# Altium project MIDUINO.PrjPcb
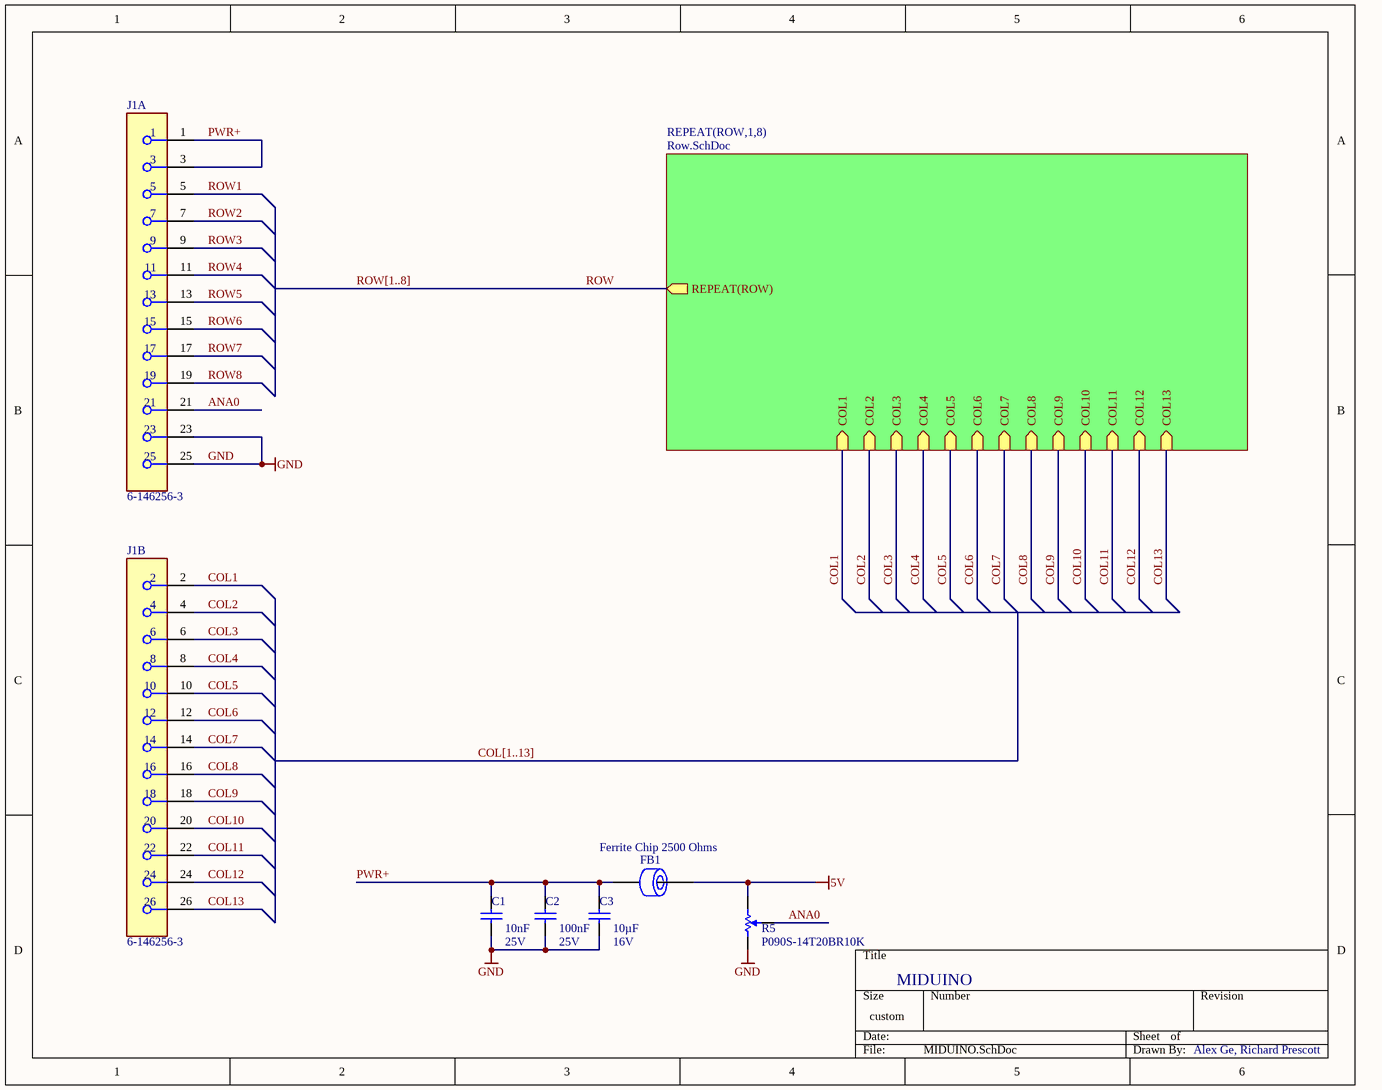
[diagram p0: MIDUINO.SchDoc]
2 sheets, 230 parts. Net scope: hierarchical (ports join the sheet entries above them; power ports are global).
Board file: MIDUINO.PcbDoc
Sheets:
  MIDUINO.SchDoc
    ROW1 = Row.SchDoc
    ROW2 = Row.SchDoc
    ROW3 = Row.SchDoc
    ROW4 = Row.SchDoc
    ROW5 = Row.SchDoc
    ROW6 = Row.SchDoc
    ROW7 = Row.SchDoc
    ROW8 = Row.SchDoc

## Sheet MIDUINO.SchDoc
size 254 x 203 mm; SheetNumber: 1; SheetTotal: 2

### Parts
C1  Val: 10nF  Vol: 25V  [0603_CAP]  (hidden comment: CAP 0603 0.01UF 25V 10% X7R)
C2  Val: 100nF  Vol: 25V  [0603_CAP]  (hidden comment: CAP 0603 0.1UF 25V 10% X7R)
C3  Val: 10µF  Vol: 16V  [0805_CAP_60H]  (hidden comment: CAP 0805 10UF 16V 20% X7R)
FB1  Ferrite Chip 2500 Ohms  [0603]
J1  6-146256-3  [FP-6-146256-3-MFG]  (parts A,B of 2)
R5  P090S-14T20BR10K  [RES-POT-3]

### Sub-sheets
REPEAT(ROW,1,8) = Row.SchDoc: COL1 (in), COL2 (in), COL3 (in), COL4 (in), COL5 (in), COL6 (in), COL7 (in), COL8 (in), COL9 (in), COL10 (in), COL11 (in), COL12 (in), COL13 (in), REPEAT(ROW) (out)

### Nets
5V: FB1.1 R5.3
GND: C1.1 C2.2 C3.1 J1.23 J1.25 R5.1
ANA0: J1.21 R5.2
COL1: J1.2 ; sheet REPEAT(ROW,1,8)/COL1
COL2: J1.4 ; sheet REPEAT(ROW,1,8)/COL2
COL3: J1.6 ; sheet REPEAT(ROW,1,8)/COL3
COL4: J1.8 ; sheet REPEAT(ROW,1,8)/COL4
COL5: J1.10 ; sheet REPEAT(ROW,1,8)/COL5
COL6: J1.12 ; sheet REPEAT(ROW,1,8)/COL6
COL7: J1.14 ; sheet REPEAT(ROW,1,8)/COL7
COL8: J1.16 ; sheet REPEAT(ROW,1,8)/COL8
COL9: J1.18 ; sheet REPEAT(ROW,1,8)/COL9
COL10: J1.20 ; sheet REPEAT(ROW,1,8)/COL10
COL11: J1.22 ; sheet REPEAT(ROW,1,8)/COL11
COL12: J1.24 ; sheet REPEAT(ROW,1,8)/COL12
COL13: J1.26 ; sheet REPEAT(ROW,1,8)/COL13
PWR+: C1.2 C2.1 C3.2 FB1.2 J1.1 J1.3
ROW1: J1.5  [project net ROW]
ROW2: J1.7  [project net ROW]
ROW3: J1.9  [project net ROW]
ROW4: J1.11  [project net ROW]
ROW5: J1.13  [project net ROW]
ROW6: J1.15  [project net ROW]
ROW7: J1.17  [project net ROW]
ROW8: J1.19  [project net ROW]

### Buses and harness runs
bus COL[1..13]
bus ROW[1..8]

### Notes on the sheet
- MIDUINO
- Alex Ge, Richard Prescott

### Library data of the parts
C1 = CAP 0603 0.01UF 25V 10% X7R-2: Capacitor Surface Mount 0603 Footprint 0.01UF 25V 10% Tolerance Ceramic X7R; Manufacturer: Various; PCB Package: 0603; Description in Visual: Cap SMT 0603 0.01UF 25V 10%  Cer X7R; Value: 10nF
C2 = CAP 0603 0.1UF 25V 10% X7R-4: Capacitor Surface Mount 0603 Footprint 0.1UF 25V 10% Tolerance Ceramic X7R; Manufacturer: Various; PCB Package: 0603; Description in Visual: Cap SMT 0603 0.1UF 25V 10%  Cer X7R; Value: 100nF
C3 = CAP 0805 10UF 16V 20% X7R-2: Capacitor Surface Mount 0805 Footprint 10UF 16V 20% Tolerance Ceramic X7R; Manufacturer: Various; PCB Package: 0805; Description in Visual: Cap SMT 0805 10UF 16V 20% Ceramic X7R; Value: 10µF
FB1 = MMZ1608A252B-2: Ferrite Chip 200 mA 2500 Ohms Differential Mode - Single 0603 Footprint; Manufacturer: TDK; Description in Visual: Ferrite SMT 200mA 2500Ohm Dif Mode 0603; Usage: Signal Line; Current (mA): 200; Frequency: 100 MHz; Impedance at Freq (ohms): 2500; DC Resistance (ohms): 0.8
J1 = CMP-03369-000069-1: CONN HEADER VERT 26POS 2.54MM; Manufacturer: TE Connectivity; Current Rating: 3A; Is Female: yes; Conn Gender: Male; Number Of Contacts: 26; Voltage Rating: 30V; Conn Orientation: Vertical
R5 = CMP-2000-06871-1: 9 mm Rotary Potentiometer, Insulated Shaft, Conductive Plastic Element, 10 KOhm, -20 to 70 degC, 3-Pin THD, RoHS, Tray; Manufacturer: BI Technologies; Actuator Type: Knurled; Power Rating: 0.03W; Tolerance: ±20%; Actuator Diameter: 0.236"(6.00mm); Other Names: 987-1277P090S14T20BR10K; Actuator Length: 0.787"(20.00mm); Number of Gangs: 1; Online Catalog: P090Series; Power (Watts): 0.03W,1/32W; Built in Switch: Detent; Resistance (Ohms): 10k; Adjustment Type: TopAdjustment; Rotation: 280°

## Sheet Row.SchDoc
size 228 x 152 mm; SheetNumber: 2; SheetTotal: 2
Used 8 times, as channels ROW1, ROW2, ROW3, ROW4, ROW5, ROW6, ROW7, ROW8. Parts and nets are listed once, with the designators drawn on the sheet.
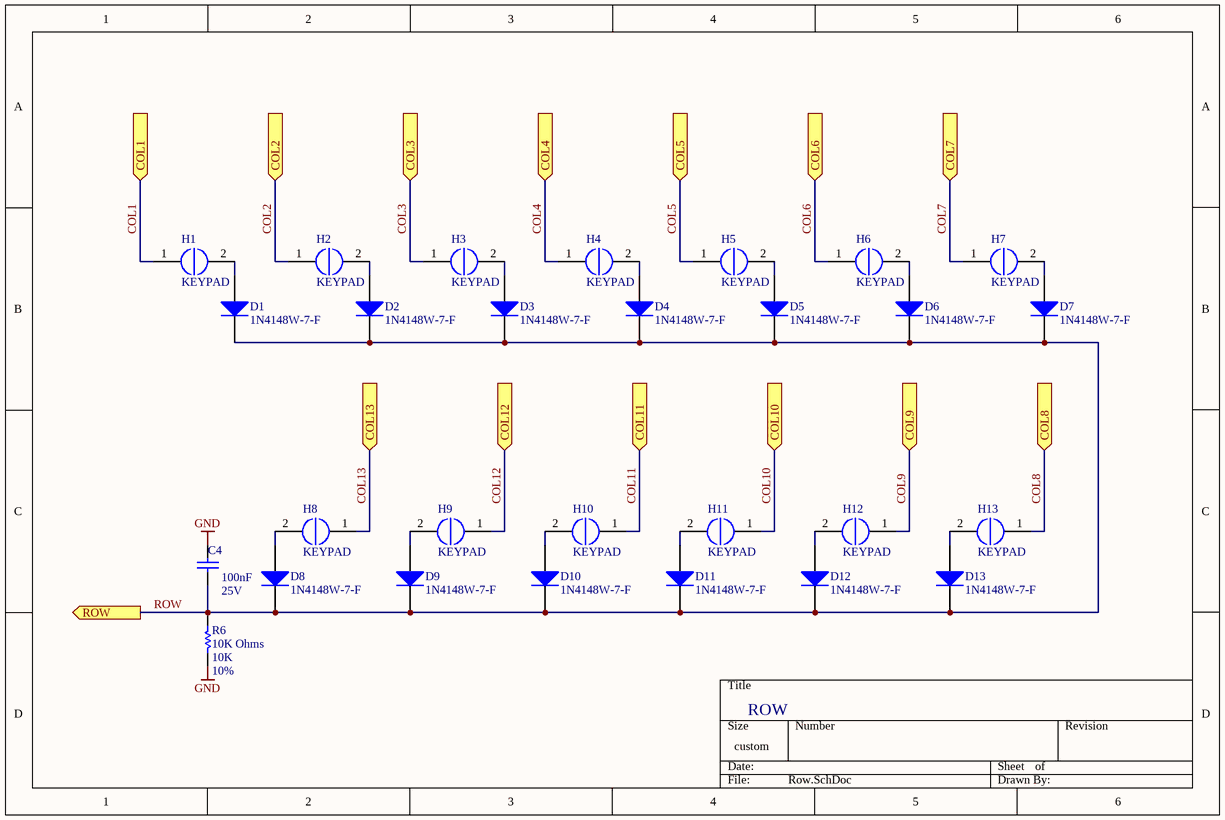
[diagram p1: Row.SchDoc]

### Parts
C4  Val: 100nF  Vol: 25V  [0603_CAP]  (hidden comment: CAP 0603 0.1UF 25V 10% X7R)
D1  1N4148W-7-F  [DIOD-SOD123-2_V]
D2  1N4148W-7-F  [DIOD-SOD123-2_V]
D3  1N4148W-7-F  [DIOD-SOD123-2_V]
D4  1N4148W-7-F  [DIOD-SOD123-2_V]
D5  1N4148W-7-F  [DIOD-SOD123-2_V]
D6  1N4148W-7-F  [DIOD-SOD123-2_V]
D7  1N4148W-7-F  [DIOD-SOD123-2_V]
D8  1N4148W-7-F  [DIOD-SOD123-2_V]
D9  1N4148W-7-F  [DIOD-SOD123-2_V]
D10  1N4148W-7-F  [DIOD-SOD123-2_V]
D11  1N4148W-7-F  [DIOD-SOD123-2_V]
D12  1N4148W-7-F  [DIOD-SOD123-2_V]
D13  1N4148W-7-F  [DIOD-SOD123-2_V]
H1  KEYPAD  [KEYPAD-Footprint-1]
H2  KEYPAD  [KEYPAD-Footprint-1]
H3  KEYPAD  [KEYPAD-Footprint-1]
H4  KEYPAD  [KEYPAD-Footprint-1]
H5  KEYPAD  [KEYPAD-Footprint-1]
H6  KEYPAD  [KEYPAD-Footprint-1]
H7  KEYPAD  [KEYPAD-Footprint-1]
H8  KEYPAD  [KEYPAD-Footprint-1]
H9  KEYPAD  [KEYPAD-Footprint-1]
H10  KEYPAD  [KEYPAD-Footprint-1]
H11  KEYPAD  [KEYPAD-Footprint-1]
H12  KEYPAD  [KEYPAD-Footprint-1]
H13  KEYPAD  [KEYPAD-Footprint-1]
R6  10K Ohms  Val: 10K  Tol: 10%  [0603_RES]

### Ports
COL1 (in), COL2 (in), COL3 (in), COL4 (in), COL5 (in), COL6 (in), COL7 (in), COL8 (in), COL9 (in), COL10 (in), COL11 (in), COL12 (in), COL13 (in), ROW (out)

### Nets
GND: C4.1 R6.1
COL1: H1.1 ; port COL1
COL2: H2.1 ; port COL2
COL3: H3.1 ; port COL3
COL4: H4.1 ; port COL4
COL5: H5.1 ; port COL5
COL6: H6.1 ; port COL6
COL7: H7.1 ; port COL7
COL8: H13.1 ; port COL8
COL9: H12.1 ; port COL9
COL10: H11.1 ; port COL10
COL11: H10.1 ; port COL11
COL12: H9.1 ; port COL12
COL13: H8.1 ; port COL13
ROW: C4.2 D1.2(K) D2.2(K) D3.2(K) D4.2(K) D5.2(K) D6.2(K) D7.2(K) D8.2(K) D9.2(K) D10.2(K) D11.2(K) D12.2(K) D13.2(K) R6.2 ; port ROW
NetD1_1: D1.1(A) H1.2
NetD2_1: D2.1(A) H2.2
NetD3_1: D3.1(A) H3.2
NetD4_1: D4.1(A) H4.2
NetD5_1: D5.1(A) H5.2
NetD6_1: D6.1(A) H6.2
NetD7_1: D7.1(A) H7.2
NetD8_1: D8.1(A) H8.2
NetD9_1: D9.1(A) H9.2
NetD10_1: D10.1(A) H10.2
NetD11_1: D11.1(A) H11.2
NetD12_1: D12.1(A) H12.2
NetD13_1: D13.1(A) H13.2

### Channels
ROW1: designators end in _ROW1; ports COL1=COL1 COL2=COL2 COL3=COL3 COL4=COL4 COL5=COL5 COL6=COL6 COL7=COL7 COL8=COL8 COL9=COL9 COL10=COL10 COL11=COL11 COL12=COL12 COL13=COL13 ROW=ROW
ROW2: designators end in _ROW2; ports COL1=COL1 COL2=COL2 COL3=COL3 COL4=COL4 COL5=COL5 COL6=COL6 COL7=COL7 COL8=COL8 COL9=COL9 COL10=COL10 COL11=COL11 COL12=COL12 COL13=COL13 ROW=ROW
ROW3: designators end in _ROW3; ports COL1=COL1 COL2=COL2 COL3=COL3 COL4=COL4 COL5=COL5 COL6=COL6 COL7=COL7 COL8=COL8 COL9=COL9 COL10=COL10 COL11=COL11 COL12=COL12 COL13=COL13 ROW=ROW
ROW4: designators end in _ROW4; ports COL1=COL1 COL2=COL2 COL3=COL3 COL4=COL4 COL5=COL5 COL6=COL6 COL7=COL7 COL8=COL8 COL9=COL9 COL10=COL10 COL11=COL11 COL12=COL12 COL13=COL13 ROW=ROW
ROW5: designators end in _ROW5; ports COL1=COL1 COL2=COL2 COL3=COL3 COL4=COL4 COL5=COL5 COL6=COL6 COL7=COL7 COL8=COL8 COL9=COL9 COL10=COL10 COL11=COL11 COL12=COL12 COL13=COL13 ROW=ROW
ROW6: designators end in _ROW6; ports COL1=COL1 COL2=COL2 COL3=COL3 COL4=COL4 COL5=COL5 COL6=COL6 COL7=COL7 COL8=COL8 COL9=COL9 COL10=COL10 COL11=COL11 COL12=COL12 COL13=COL13 ROW=ROW
ROW7: designators end in _ROW7; ports COL1=COL1 COL2=COL2 COL3=COL3 COL4=COL4 COL5=COL5 COL6=COL6 COL7=COL7 COL8=COL8 COL9=COL9 COL10=COL10 COL11=COL11 COL12=COL12 COL13=COL13 ROW=ROW
ROW8: designators end in _ROW8; ports COL1=COL1 COL2=COL2 COL3=COL3 COL4=COL4 COL5=COL5 COL6=COL6 COL7=COL7 COL8=COL8 COL9=COL9 COL10=COL10 COL11=COL11 COL12=COL12 COL13=COL13 ROW=ROW

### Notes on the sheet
- ROW

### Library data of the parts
C4 = CAP 0603 0.1UF 25V 10% X7R-4: as C2 on sheet MIDUINO
D1-D13 = CMP-2000-04932-2: Fast Switching Diode, 100 V, 0.15 A, -65 to 150 degC, 2-Pin?SOD123, RoHS, Tape and Reel; Recovery Time: 4ns; Brand: DiodesIncorporated; Unit Weight: 0.000353oz; Max Surge Current: 2A; Peak Reverse Voltage: 100V; Ir - Reverse Current: 1uA; Vf - Forward Voltage: 1.25V; Configuration: Single; If - Forward Current: 0.15A
H1-H13 = CMP-00322-7: Piano keypad
R6 = RES 0603 10K 10%-1: Resistor Surface Mount, 10K Ohms, 0603 Footprint, 10% Tolerance 0.1W; Manufacturer P/N: Various; Description in Visual: Res SMT 10K 0603  10%  0.1W; PCB Package: 0603

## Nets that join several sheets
GND: MIDUINO (6 pins), ROW1 (C4_ROW1.1 R6_ROW1.1), ROW2 (C4_ROW2.1 R6_ROW2.1), ROW3 (C4_ROW3.1 R6_ROW3.1), ROW4 (C4_ROW4.1 R6_ROW4.1), ROW5 (C4_ROW5.1 R6_ROW5.1), ROW6 (C4_ROW6.1 R6_ROW6.1), ROW7 (C4_ROW7.1 R6_ROW7.1), ROW8 (C4_ROW8.1 R6_ROW8.1)
COL1: MIDUINO (J1.2), ROW1 (H1_ROW1.1), ROW2 (H1_ROW2.1), ROW3 (H1_ROW3.1), ROW4 (H1_ROW4.1), ROW5 (H1_ROW5.1), ROW6 (H1_ROW6.1), ROW7 (H1_ROW7.1), ROW8 (H1_ROW8.1)
COL2: MIDUINO (J1.4), ROW1 (H2_ROW1.1), ROW2 (H2_ROW2.1), ROW3 (H2_ROW3.1), ROW4 (H2_ROW4.1), ROW5 (H2_ROW5.1), ROW6 (H2_ROW6.1), ROW7 (H2_ROW7.1), ROW8 (H2_ROW8.1)
COL3: MIDUINO (J1.6), ROW1 (H3_ROW1.1), ROW2 (H3_ROW2.1), ROW3 (H3_ROW3.1), ROW4 (H3_ROW4.1), ROW5 (H3_ROW5.1), ROW6 (H3_ROW6.1), ROW7 (H3_ROW7.1), ROW8 (H3_ROW8.1)
COL4: MIDUINO (J1.8), ROW1 (H4_ROW1.1), ROW2 (H4_ROW2.1), ROW3 (H4_ROW3.1), ROW4 (H4_ROW4.1), ROW5 (H4_ROW5.1), ROW6 (H4_ROW6.1), ROW7 (H4_ROW7.1), ROW8 (H4_ROW8.1)
COL5: MIDUINO (J1.10), ROW1 (H5_ROW1.1), ROW2 (H5_ROW2.1), ROW3 (H5_ROW3.1), ROW4 (H5_ROW4.1), ROW5 (H5_ROW5.1), ROW6 (H5_ROW6.1), ROW7 (H5_ROW7.1), ROW8 (H5_ROW8.1)
COL6: MIDUINO (J1.12), ROW1 (H6_ROW1.1), ROW2 (H6_ROW2.1), ROW3 (H6_ROW3.1), ROW4 (H6_ROW4.1), ROW5 (H6_ROW5.1), ROW6 (H6_ROW6.1), ROW7 (H6_ROW7.1), ROW8 (H6_ROW8.1)
COL7: MIDUINO (J1.14), ROW1 (H7_ROW1.1), ROW2 (H7_ROW2.1), ROW3 (H7_ROW3.1), ROW4 (H7_ROW4.1), ROW5 (H7_ROW5.1), ROW6 (H7_ROW6.1), ROW7 (H7_ROW7.1), ROW8 (H7_ROW8.1)
COL8: MIDUINO (J1.16), ROW1 (H13_ROW1.1), ROW2 (H13_ROW2.1), ROW3 (H13_ROW3.1), ROW4 (H13_ROW4.1), ROW5 (H13_ROW5.1), ROW6 (H13_ROW6.1), ROW7 (H13_ROW7.1), ROW8 (H13_ROW8.1)
COL9: MIDUINO (J1.18), ROW1 (H12_ROW1.1), ROW2 (H12_ROW2.1), ROW3 (H12_ROW3.1), ROW4 (H12_ROW4.1), ROW5 (H12_ROW5.1), ROW6 (H12_ROW6.1), ROW7 (H12_ROW7.1), ROW8 (H12_ROW8.1)
COL10: MIDUINO (J1.20), ROW1 (H11_ROW1.1), ROW2 (H11_ROW2.1), ROW3 (H11_ROW3.1), ROW4 (H11_ROW4.1), ROW5 (H11_ROW5.1), ROW6 (H11_ROW6.1), ROW7 (H11_ROW7.1), ROW8 (H11_ROW8.1)
COL11: MIDUINO (J1.22), ROW1 (H10_ROW1.1), ROW2 (H10_ROW2.1), ROW3 (H10_ROW3.1), ROW4 (H10_ROW4.1), ROW5 (H10_ROW5.1), ROW6 (H10_ROW6.1), ROW7 (H10_ROW7.1), ROW8 (H10_ROW8.1)
COL12: MIDUINO (J1.24), ROW1 (H9_ROW1.1), ROW2 (H9_ROW2.1), ROW3 (H9_ROW3.1), ROW4 (H9_ROW4.1), ROW5 (H9_ROW5.1), ROW6 (H9_ROW6.1), ROW7 (H9_ROW7.1), ROW8 (H9_ROW8.1)
COL13: MIDUINO (J1.26), ROW1 (H8_ROW1.1), ROW2 (H8_ROW2.1), ROW3 (H8_ROW3.1), ROW4 (H8_ROW4.1), ROW5 (H8_ROW5.1), ROW6 (H8_ROW6.1), ROW7 (H8_ROW7.1), ROW8 (H8_ROW8.1)
ROW: MIDUINO (J1.5), ROW1 (15 pins)
ROW: MIDUINO (J1.7), ROW2 (15 pins)
ROW: MIDUINO (J1.9), ROW3 (15 pins)
ROW: MIDUINO (J1.11), ROW4 (15 pins)
ROW: MIDUINO (J1.13), ROW5 (15 pins)
ROW: MIDUINO (J1.15), ROW6 (15 pins)
ROW: MIDUINO (J1.17), ROW7 (15 pins)
ROW: MIDUINO (J1.19), ROW8 (15 pins)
